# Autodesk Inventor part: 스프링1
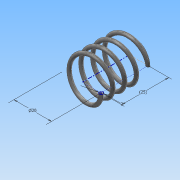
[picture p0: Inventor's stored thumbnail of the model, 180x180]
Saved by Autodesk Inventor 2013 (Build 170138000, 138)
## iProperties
Created: 2016-07
Part Number: 스프링1
Material: 스테인리스강
Document SubType Name: Modeling
Designer: Administrator
Mass: 6.2731 g
Surface Area: 15.7615 cm^2
Volume: 0.776373 cm^3
Density: 8.08 g/cm^3
Author: Administrator
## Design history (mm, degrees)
sketch "스케치1"
  geometry: L1 (0, 0)-(10, 0); L2 (10, 0)-(10, 25); L3 (10, 25)-(0, 25); L4 (0, 25)-(0, 0); C1 r 1 at (10, 0)
  constraints: 8 end point, 2 parallel, 1 centre point, 1 coincident, 1 horizontal, 1 perpendicular
  dimensions: "d0" = 20 diameter of L2 L4; "d2" = 2 diameter of C1; "d3" = 25 distance of L1.end L2.end (derived)
feature "코일1" pitch "d4" = 10; turns "d6" = 4; dims "d5" = 25 (= d3), "d7" = 0, angle "d8" = 90 deg, angle "d9" = 90 deg, "d10" = 0, "d11" = 0
sketch "스케치2"
  geometry: L1 (-11, 0)-(-9, 0) reference; 1 further point
  constraints: 1 horizontal alignment
extrude "돌출1" cut sketch "스케치2" distance "d12" = 10; taper "d13" = 0 deg
node "작업 평면1"
sketch "스케치3"
  geometry: L1 (11, 0)-(9, 0) reference; 1 further point
  constraints: 1 horizontal alignment
extrude "돌출2" cut sketch "스케치3" distance "d14" = 10; taper "d15" = 0 deg
node "솔리드1"
node "절단 모서리 투영1"
node "절단 모서리 투영2"
